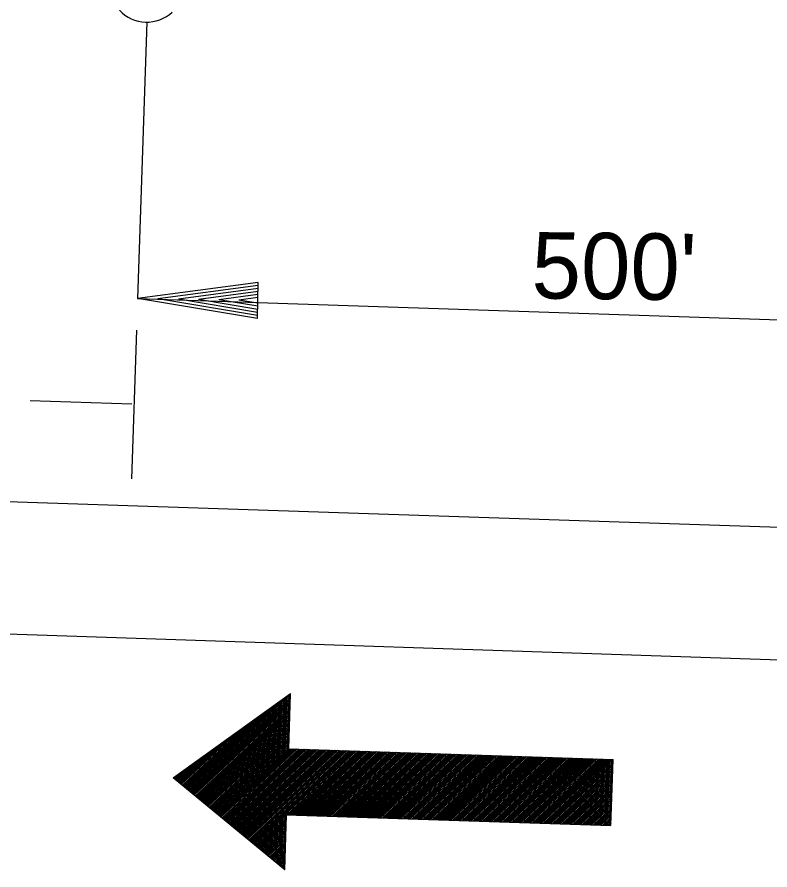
# Model space of a CAD drawing. Extents: x 977269 to 979191, y 1525946 to 1526973.
# Drawn here: x 978366.8 to 978434.9, y 1526646.2 to 1526723.4 of the extents above; entities that cross this region are included whole.
import ezdxf

# ---------------------------------------------------------------- set-up
doc = ezdxf.new("R2010")
doc.units = 0
for name, color, linetype in [('R_Border', 7, 'Continuous'), ('STAMP', 7, 'Continuous'), ('STAMP_PP', 7, 'Continuous')]:
    doc.layers.add(name, color=color, linetype=linetype)

msp = doc.modelspace()

# ---------------------------------------------------------------- linework, layer by layer
at = {"layer": 'R_Border'}
for p, q in [((978391.361, 1526662.043), (978382.238, 1526653.509)), ((978391.57, 1526662.101), (978382.316, 1526653.444)), ((978391.565, 1526661.96), (978382.393, 1526653.38)), ((978390.729, 1526661.588), (978382.16, 1526653.573)), ((978391.56, 1526661.818), (978382.471, 1526653.316)), ((978391.555, 1526661.677), (978382.549, 1526653.252)), ((978391.551, 1526661.536), (978382.627, 1526653.188)), ((978391.546, 1526661.394), (978382.704, 1526653.123)), ((978391.541, 1526661.253), (978382.782, 1526653.059)), ((978389.465, 1526660.68), (978382.004, 1526653.701)), ((978390.097, 1526661.134), (978382.082, 1526653.637)), ((978391.537, 1526661.112), (978382.86, 1526652.995)), ((978391.532, 1526660.97), (978382.938, 1526652.931)), ((978391.527, 1526660.829), (978383.016, 1526652.867)), ((978391.522, 1526660.688), (978383.093, 1526652.803)), ((978391.518, 1526660.546), (978383.171, 1526652.738)), ((978391.513, 1526660.405), (978383.249, 1526652.674)), ((978388.201, 1526659.772), (978381.849, 1526653.829)), ((978388.833, 1526660.226), (978381.927, 1526653.765)), ((978391.508, 1526660.264), (978383.327, 1526652.61)), ((978391.504, 1526660.122), (978383.404, 1526652.546)), ((978391.499, 1526659.981), (978383.482, 1526652.482)), ((978391.494, 1526659.84), (978383.56, 1526652.418)), ((978391.489, 1526659.698), (978383.638, 1526652.353)), ((978386.937, 1526658.863), (978381.693, 1526653.958)), ((978387.569, 1526659.317), (978381.771, 1526653.894)), ((978391.485, 1526659.557), (978383.716, 1526652.289)), ((978391.48, 1526659.416), (978383.793, 1526652.225)), ((978391.475, 1526659.274), (978383.871, 1526652.161)), ((978391.471, 1526659.133), (978383.949, 1526652.097)), ((978391.466, 1526658.992), (978384.027, 1526652.032)), ((978386.305, 1526658.409), (978381.616, 1526654.022)), ((978391.461, 1526658.85), (978384.104, 1526651.968)), ((978391.457, 1526658.709), (978384.182, 1526651.904)), ((978391.452, 1526658.568), (978384.26, 1526651.84)), ((978391.447, 1526658.426), (978384.338, 1526651.776)), ((978391.442, 1526658.285), (978384.416, 1526651.712)), ((978391.438, 1526658.144), (978384.493, 1526651.647)), ((978385.041, 1526657.501), (978381.46, 1526654.15)), ((978385.673, 1526657.955), (978381.538, 1526654.086)), ((978391.433, 1526658.002), (978384.571, 1526651.583)), ((978391.428, 1526657.861), (978384.649, 1526651.519)), ((978391.424, 1526657.72), (978384.727, 1526651.455)), ((978391.419, 1526657.578), (978384.804, 1526651.391)), ((978391.414, 1526657.437), (978384.882, 1526651.327)), ((978383.778, 1526656.592), (978381.304, 1526654.279)), ((978384.41, 1526657.046), (978381.382, 1526654.214)), ((978391.409, 1526657.295), (978384.96, 1526651.262)), ((978391.463, 1526657.209), (978385.038, 1526651.198)), ((978391.604, 1526657.204), (978385.116, 1526651.134)), ((978391.746, 1526657.199), (978385.193, 1526651.07)), ((978391.887, 1526657.195), (978385.271, 1526651.006)), ((978392.028, 1526657.19), (978385.349, 1526650.942)), ((978392.17, 1526657.185), (978385.427, 1526650.877)), ((978392.311, 1526657.18), (978385.504, 1526650.813)), ((978392.452, 1526657.176), (978385.582, 1526650.749)), ((978392.594, 1526657.171), (978385.66, 1526650.685)), ((978392.735, 1526657.166), (978385.738, 1526650.621)), ((978392.876, 1526657.162), (978385.816, 1526650.556)), ((978393.018, 1526657.157), (978385.893, 1526650.492)), ((978393.159, 1526657.152), (978385.971, 1526650.428)), ((978393.3, 1526657.147), (978386.049, 1526650.364)), ((978393.442, 1526657.143), (978386.127, 1526650.3)), ((978393.583, 1526657.138), (978386.204, 1526650.236)), ((978393.724, 1526657.133), (978386.282, 1526650.171)), ((978393.866, 1526657.129), (978386.36, 1526650.107)), ((978394.007, 1526657.124), (978386.438, 1526650.043)), ((978394.149, 1526657.119), (978386.516, 1526649.979)), ((978394.29, 1526657.114), (978386.593, 1526649.915)), ((978394.431, 1526657.11), (978386.671, 1526649.851)), ((978394.573, 1526657.105), (978386.749, 1526649.786)), ((978394.714, 1526657.1), (978386.827, 1526649.722)), ((978394.855, 1526657.096), (978386.904, 1526649.658)), ((978394.997, 1526657.091), (978386.982, 1526649.594)), ((978395.138, 1526657.086), (978387.06, 1526649.53)), ((978395.279, 1526657.081), (978387.138, 1526649.465)), ((978395.421, 1526657.077), (978387.216, 1526649.401)), ((978395.562, 1526657.072), (978387.293, 1526649.337)), ((978395.703, 1526657.067), (978387.371, 1526649.273)), ((978395.845, 1526657.063), (978387.449, 1526649.209)), ((978395.986, 1526657.058), (978387.527, 1526649.145)), ((978396.127, 1526657.053), (978387.604, 1526649.08)), ((978396.269, 1526657.048), (978387.682, 1526649.016)), ((978396.41, 1526657.044), (978387.76, 1526648.952)), ((978396.551, 1526657.039), (978387.838, 1526648.888)), ((978396.693, 1526657.034), (978387.916, 1526648.824)), ((978396.834, 1526657.03), (978387.993, 1526648.76)), ((978396.975, 1526657.025), (978388.071, 1526648.695)), ((978397.117, 1526657.02), (978388.149, 1526648.631)), ((978397.258, 1526657.015), (978388.227, 1526648.567)), ((978397.399, 1526657.011), (978391.219, 1526651.229)), ((978397.541, 1526657.006), (978391.36, 1526651.224)), ((978397.682, 1526657.001), (978391.501, 1526651.22)), ((978397.823, 1526656.997), (978391.643, 1526651.215)), ((978397.965, 1526656.992), (978391.784, 1526651.21)), ((978398.106, 1526656.987), (978391.925, 1526651.205)), ((978398.247, 1526656.982), (978392.067, 1526651.201)), ((978398.389, 1526656.978), (978392.208, 1526651.196)), ((978398.53, 1526656.973), (978392.349, 1526651.191)), ((978398.671, 1526656.968), (978392.491, 1526651.187)), ((978398.813, 1526656.964), (978392.632, 1526651.182)), ((978398.954, 1526656.959), (978392.773, 1526651.177)), ((978399.096, 1526656.954), (978392.915, 1526651.172)), ((978399.237, 1526656.949), (978393.056, 1526651.168)), ((978399.378, 1526656.945), (978393.197, 1526651.163)), ((978399.52, 1526656.94), (978393.339, 1526651.158)), ((978399.661, 1526656.935), (978393.48, 1526651.154)), ((978399.802, 1526656.931), (978393.621, 1526651.149)), ((978399.944, 1526656.926), (978393.763, 1526651.144)), ((978400.085, 1526656.921), (978393.904, 1526651.139)), ((978400.226, 1526656.917), (978394.045, 1526651.135)), ((978400.368, 1526656.912), (978394.187, 1526651.13)), ((978400.509, 1526656.907), (978394.328, 1526651.125)), ((978400.65, 1526656.902), (978394.47, 1526651.121)), ((978400.792, 1526656.898), (978394.611, 1526651.116)), ((978400.933, 1526656.893), (978394.752, 1526651.111)), ((978401.074, 1526656.888), (978394.894, 1526651.106)), ((978401.216, 1526656.884), (978395.035, 1526651.102)), ((978401.357, 1526656.879), (978395.176, 1526651.097)), ((978401.498, 1526656.874), (978395.318, 1526651.092)), ((978401.64, 1526656.869), (978395.459, 1526651.088)), ((978401.781, 1526656.865), (978395.6, 1526651.083)), ((978401.922, 1526656.86), (978395.742, 1526651.078)), ((978402.064, 1526656.855), (978395.883, 1526651.073)), ((978402.205, 1526656.851), (978396.024, 1526651.069)), ((978402.346, 1526656.846), (978396.166, 1526651.064)), ((978402.488, 1526656.841), (978396.307, 1526651.059)), ((978402.629, 1526656.836), (978396.448, 1526651.055)), ((978402.77, 1526656.832), (978396.59, 1526651.05)), ((978402.912, 1526656.827), (978396.731, 1526651.045)), ((978403.053, 1526656.822), (978396.872, 1526651.04)), ((978403.194, 1526656.818), (978397.014, 1526651.036)), ((978403.336, 1526656.813), (978397.155, 1526651.031)), ((978403.477, 1526656.808), (978397.296, 1526651.026)), ((978403.618, 1526656.803), (978397.438, 1526651.022)), ((978403.76, 1526656.799), (978397.579, 1526651.017)), ((978403.901, 1526656.794), (978397.72, 1526651.012)), ((978404.043, 1526656.789), (978397.862, 1526651.007)), ((978404.184, 1526656.785), (978398.003, 1526651.003)), ((978404.325, 1526656.78), (978398.144, 1526650.998)), ((978404.467, 1526656.775), (978398.286, 1526650.993)), ((978404.608, 1526656.77), (978398.427, 1526650.989)), ((978404.749, 1526656.766), (978398.568, 1526650.984)), ((978404.891, 1526656.761), (978398.71, 1526650.979)), ((978405.032, 1526656.756), (978398.851, 1526650.974)), ((978405.173, 1526656.752), (978398.992, 1526650.97)), ((978405.315, 1526656.747), (978399.134, 1526650.965)), ((978405.456, 1526656.742), (978399.275, 1526650.96)), ((978405.597, 1526656.737), (978399.417, 1526650.956)), ((978405.739, 1526656.733), (978399.558, 1526650.951)), ((978405.88, 1526656.728), (978399.699, 1526650.946)), ((978406.021, 1526656.723), (978399.841, 1526650.941)), ((978406.163, 1526656.719), (978399.982, 1526650.937)), ((978406.304, 1526656.714), (978400.123, 1526650.932)), ((978406.445, 1526656.709), (978400.265, 1526650.927)), ((978406.587, 1526656.704), (978400.406, 1526650.923)), ((978406.728, 1526656.7), (978400.547, 1526650.918)), ((978406.869, 1526656.695), (978400.689, 1526650.913)), ((978407.011, 1526656.69), (978400.83, 1526650.908)), ((978407.152, 1526656.686), (978400.971, 1526650.904)), ((978407.293, 1526656.681), (978401.113, 1526650.899)), ((978407.435, 1526656.676), (978401.254, 1526650.894)), ((978407.576, 1526656.671), (978401.395, 1526650.89)), ((978407.717, 1526656.667), (978401.537, 1526650.885)), ((978407.859, 1526656.662), (978401.678, 1526650.88)), ((978408, 1526656.657), (978401.819, 1526650.875)), ((978408.141, 1526656.653), (978401.961, 1526650.871)), ((978408.283, 1526656.648), (978402.102, 1526650.866)), ((978408.424, 1526656.643), (978402.243, 1526650.861)), ((978408.565, 1526656.638), (978402.385, 1526650.857)), ((978408.707, 1526656.634), (978402.526, 1526650.852)), ((978408.848, 1526656.629), (978402.667, 1526650.847)), ((978408.99, 1526656.624), (978402.809, 1526650.842)), ((978409.131, 1526656.62), (978402.95, 1526650.838)), ((978409.272, 1526656.615), (978403.091, 1526650.833)), ((978409.414, 1526656.61), (978403.233, 1526650.828)), ((978409.555, 1526656.605), (978403.374, 1526650.824)), ((978409.696, 1526656.601), (978403.515, 1526650.819)), ((978409.838, 1526656.596), (978403.657, 1526650.814)), ((978409.979, 1526656.591), (978403.798, 1526650.809)), ((978410.12, 1526656.587), (978403.939, 1526650.805)), ((978410.262, 1526656.582), (978404.081, 1526650.8)), ((978410.403, 1526656.577), (978404.222, 1526650.795)), ((978410.544, 1526656.572), (978404.364, 1526650.791)), ((978410.686, 1526656.568), (978404.505, 1526650.786)), ((978410.827, 1526656.563), (978404.646, 1526650.781)), ((978410.968, 1526656.558), (978404.788, 1526650.776)), ((978411.11, 1526656.554), (978404.929, 1526650.772)), ((978411.251, 1526656.549), (978405.07, 1526650.767)), ((978383.146, 1526656.138), (978381.227, 1526654.343)), ((978411.392, 1526656.544), (978405.212, 1526650.762)), ((978411.534, 1526656.539), (978405.353, 1526650.758)), ((978411.675, 1526656.535), (978405.494, 1526650.753)), ((978411.816, 1526656.53), (978405.636, 1526650.748)), ((978411.958, 1526656.525), (978405.777, 1526650.743)), ((978412.099, 1526656.521), (978405.918, 1526650.739)), ((978412.24, 1526656.516), (978406.06, 1526650.734)), ((978412.382, 1526656.511), (978406.201, 1526650.729)), ((978412.523, 1526656.506), (978406.342, 1526650.725)), ((978412.664, 1526656.502), (978406.484, 1526650.72)), ((978412.806, 1526656.497), (978406.625, 1526650.715)), ((978412.947, 1526656.492), (978406.766, 1526650.71)), ((978413.088, 1526656.488), (978406.908, 1526650.706)), ((978413.23, 1526656.483), (978407.049, 1526650.701)), ((978413.371, 1526656.478), (978407.19, 1526650.696)), ((978413.512, 1526656.473), (978407.332, 1526650.692)), ((978413.654, 1526656.469), (978407.473, 1526650.687)), ((978413.795, 1526656.464), (978407.614, 1526650.682)), ((978413.937, 1526656.459), (978407.756, 1526650.677)), ((978414.078, 1526656.455), (978407.897, 1526650.673)), ((978414.219, 1526656.45), (978408.038, 1526650.668)), ((978414.361, 1526656.445), (978408.18, 1526650.663)), ((978414.502, 1526656.44), (978408.321, 1526650.659)), ((978414.643, 1526656.436), (978408.462, 1526650.654)), ((978414.785, 1526656.431), (978408.604, 1526650.649)), ((978414.926, 1526656.426), (978408.745, 1526650.644)), ((978415.067, 1526656.422), (978408.886, 1526650.64)), ((978415.209, 1526656.417), (978409.028, 1526650.635)), ((978415.35, 1526656.412), (978409.169, 1526650.63)), ((978415.491, 1526656.407), (978409.311, 1526650.626)), ((978415.633, 1526656.403), (978409.452, 1526650.621)), ((978415.774, 1526656.398), (978409.593, 1526650.616)), ((978415.915, 1526656.393), (978409.735, 1526650.611)), ((978416.057, 1526656.389), (978409.876, 1526650.607)), ((978416.198, 1526656.384), (978410.017, 1526650.602)), ((978416.339, 1526656.379), (978410.159, 1526650.597)), ((978416.481, 1526656.374), (978410.3, 1526650.593)), ((978416.622, 1526656.37), (978410.441, 1526650.588)), ((978416.763, 1526656.365), (978410.583, 1526650.583)), ((978416.905, 1526656.36), (978410.724, 1526650.578)), ((978417.046, 1526656.356), (978410.865, 1526650.574)), ((978417.187, 1526656.351), (978411.007, 1526650.569)), ((978417.329, 1526656.346), (978411.148, 1526650.564)), ((978417.47, 1526656.341), (978411.289, 1526650.56)), ((978417.611, 1526656.337), (978411.431, 1526650.555)), ((978417.753, 1526656.332), (978411.572, 1526650.55)), ((978417.894, 1526656.327), (978411.713, 1526650.545)), ((978418.035, 1526656.323), (978411.855, 1526650.541)), ((978418.177, 1526656.318), (978411.996, 1526650.536)), ((978418.318, 1526656.313), (978412.137, 1526650.531)), ((978418.459, 1526656.308), (978412.279, 1526650.527)), ((978418.601, 1526656.304), (978412.42, 1526650.522)), ((978418.742, 1526656.299), (978412.561, 1526650.517)), ((978418.884, 1526656.294), (978412.703, 1526650.512)), ((978419.025, 1526656.29), (978412.844, 1526650.508)), ((978419.166, 1526656.285), (978412.985, 1526650.503)), ((978419.308, 1526656.28), (978413.127, 1526650.498)), ((978419.449, 1526656.275), (978413.268, 1526650.494)), ((978419.59, 1526656.271), (978413.409, 1526650.489)), ((978419.732, 1526656.266), (978413.551, 1526650.484)), ((978419.873, 1526656.261), (978413.692, 1526650.479)), ((978420.014, 1526656.257), (978413.833, 1526650.475)), ((978420.156, 1526656.252), (978413.975, 1526650.47)), ((978420.297, 1526656.247), (978414.116, 1526650.465)), ((978420.438, 1526656.242), (978414.258, 1526650.461)), ((978420.58, 1526656.238), (978414.399, 1526650.456)), ((978420.721, 1526656.233), (978414.54, 1526650.451)), ((978420.733, 1526656.108), (978414.682, 1526650.447)), ((978420.729, 1526655.966), (978414.823, 1526650.442)), ((978420.724, 1526655.825), (978414.964, 1526650.437)), ((978381.882, 1526655.23), (978381.071, 1526654.471)), ((978382.514, 1526655.684), (978381.149, 1526654.407)), ((978420.719, 1526655.684), (978415.106, 1526650.432)), ((978420.715, 1526655.542), (978415.247, 1526650.428)), ((978420.71, 1526655.401), (978415.388, 1526650.423)), ((978420.705, 1526655.26), (978415.53, 1526650.418)), ((978420.7, 1526655.118), (978415.671, 1526650.414)), ((978381.25, 1526654.775), (978380.993, 1526654.535)), ((978420.696, 1526654.977), (978415.812, 1526650.409)), ((978420.691, 1526654.836), (978415.954, 1526650.404)), ((978420.686, 1526654.694), (978416.095, 1526650.399)), ((978420.682, 1526654.553), (978416.236, 1526650.395)), ((978420.677, 1526654.412), (978416.378, 1526650.39)), ((978420.672, 1526654.27), (978416.519, 1526650.385)), ((978420.667, 1526654.129), (978416.66, 1526650.381)), ((978420.663, 1526653.988), (978416.802, 1526650.376)), ((978420.658, 1526653.846), (978416.943, 1526650.371)), ((978420.653, 1526653.705), (978417.084, 1526650.366)), ((978420.649, 1526653.564), (978417.226, 1526650.362)), ((978420.644, 1526653.422), (978417.367, 1526650.357)), ((978420.639, 1526653.281), (978417.508, 1526650.352)), ((978420.634, 1526653.14), (978417.65, 1526650.348)), ((978420.63, 1526652.998), (978417.791, 1526650.343)), ((978420.625, 1526652.857), (978417.932, 1526650.338)), ((978420.62, 1526652.716), (978418.074, 1526650.333)), ((978420.616, 1526652.574), (978418.215, 1526650.329)), ((978420.611, 1526652.433), (978418.356, 1526650.324)), ((978420.606, 1526652.292), (978418.498, 1526650.319)), ((978420.601, 1526652.15), (978418.639, 1526650.315)), ((978420.597, 1526652.009), (978418.78, 1526650.31)), ((978391.207, 1526651.218), (978388.304, 1526648.503)), ((978420.592, 1526651.868), (978418.922, 1526650.305)), ((978420.587, 1526651.726), (978419.063, 1526650.3)), ((978420.583, 1526651.585), (978419.205, 1526650.296)), ((978420.578, 1526651.443), (978419.346, 1526650.291)), ((978420.573, 1526651.302), (978419.487, 1526650.286)), ((978420.568, 1526651.161), (978419.629, 1526650.282)), ((978391.202, 1526651.076), (978388.382, 1526648.439)), ((978391.197, 1526650.935), (978388.46, 1526648.374)), ((978391.193, 1526650.794), (978388.538, 1526648.31)), ((978391.188, 1526650.652), (978388.616, 1526648.246)), ((978391.183, 1526650.511), (978388.693, 1526648.182)), ((978420.564, 1526651.019), (978419.77, 1526650.277)), ((978420.559, 1526650.878), (978419.911, 1526650.272)), ((978420.554, 1526650.737), (978420.053, 1526650.267)), ((978420.55, 1526650.595), (978420.194, 1526650.263)), ((978420.545, 1526650.454), (978420.335, 1526650.258)), ((978391.178, 1526650.37), (978388.771, 1526648.118)), ((978391.174, 1526650.228), (978388.849, 1526648.054)), ((978391.169, 1526650.087), (978388.927, 1526647.989)), ((978391.164, 1526649.946), (978389.004, 1526647.925)), ((978391.16, 1526649.804), (978389.082, 1526647.861)), ((978391.155, 1526649.663), (978389.16, 1526647.797)), ((978420.54, 1526650.313), (978420.477, 1526650.253)), ((978391.15, 1526649.522), (978389.238, 1526647.733)), ((978391.145, 1526649.38), (978389.316, 1526647.669)), ((978391.141, 1526649.239), (978389.393, 1526647.604)), ((978391.136, 1526649.098), (978389.471, 1526647.54)), ((978391.131, 1526648.956), (978389.549, 1526647.476)), ((978391.127, 1526648.815), (978389.627, 1526647.412)), ((978391.122, 1526648.674), (978389.704, 1526647.348)), ((978391.117, 1526648.532), (978389.782, 1526647.283)), ((978391.112, 1526648.391), (978389.86, 1526647.219)), ((978391.108, 1526648.25), (978389.938, 1526647.155)), ((978391.103, 1526648.108), (978390.016, 1526647.091)), ((978391.098, 1526647.967), (978390.093, 1526647.027)), ((978391.094, 1526647.826), (978390.171, 1526646.963)), ((978391.089, 1526647.684), (978390.249, 1526646.898)), ((978391.084, 1526647.543), (978390.327, 1526646.834)), ((978391.079, 1526647.402), (978390.404, 1526646.77)), ((978391.075, 1526647.26), (978390.482, 1526646.706)), ((978391.07, 1526647.119), (978390.56, 1526646.642)), ((978391.065, 1526646.977), (978390.638, 1526646.578)), ((978391.061, 1526646.836), (978390.716, 1526646.513)), ((978391.056, 1526646.695), (978390.793, 1526646.449)), ((978391.051, 1526646.553), (978390.871, 1526646.385)), ((978391.046, 1526646.412), (978390.949, 1526646.321)), ((978391.042, 1526646.271), (978391.027, 1526646.257))]:
    msp.add_line(p, q, dxfattribs=at)
at = {"layer": 'STAMP'}
for p, q in [((978378.569, 1526722.924), (978377.736, 1526697.936)), ((978388.644, 1526699.382), (978377.736, 1526697.936)), ((978388.639, 1526699.11), (978379.554, 1526697.907)), ((978388.585, 1526696.118), (978388.644, 1526699.382)), ((978388.634, 1526698.829), (978381.422, 1526697.872)), ((978388.63, 1526698.561), (978383.235, 1526697.843)), ((978388.625, 1526698.28), (978385.08, 1526697.809)), ((978377.736, 1526697.936), (978477.68, 1526694.603)), ((978388.585, 1526696.118), (978377.736, 1526697.936)), ((978388.589, 1526696.39), (978379.554, 1526697.907)), ((978388.594, 1526696.666), (978381.422, 1526697.872)), ((978388.599, 1526696.938), (978383.235, 1526697.843)), ((978388.603, 1526697.22), (978385.08, 1526697.809)), ((978388.621, 1526698.004), (978386.894, 1526697.78)), ((978388.608, 1526697.492), (978386.894, 1526697.78)), ((978377.64, 1526695.068), (978377.191, 1526681.61)), ((978377.222, 1526688.378), (978368.037, 1526688.684)), ((978730.566, 1526667.371), (978296.799, 1526681.836)), ((978730.167, 1526655.408), (978296.4, 1526669.873)), ((978380.957, 1526654.565), (978391.573, 1526662.195)), ((978391.407, 1526657.211), (978391.573, 1526662.195)), ((978391.407, 1526657.211), (978420.738, 1526656.233)), ((978420.538, 1526650.251), (978420.738, 1526656.233)), ((978391.041, 1526646.245), (978380.957, 1526654.565)), ((978391.041, 1526646.245), (978391.207, 1526651.229)), ((978391.207, 1526651.229), (978420.538, 1526650.251))]:
    msp.add_line(p, q, dxfattribs=at)
at = {"layer": 'STAMP_PP'}
msp.add_arc((978378.559, 1526726.299), 3.375, 223.09005, 313.09005, dxfattribs=at)

# ---------------------------------------------------------------- texts
at = {"layer": 'STAMP'}
msp.add_text("500'", height=6, rotation=359.32044, dxfattribs=at).set_placement((978413.342, 1526697.943))

doc.saveas('drawing.dxf')
